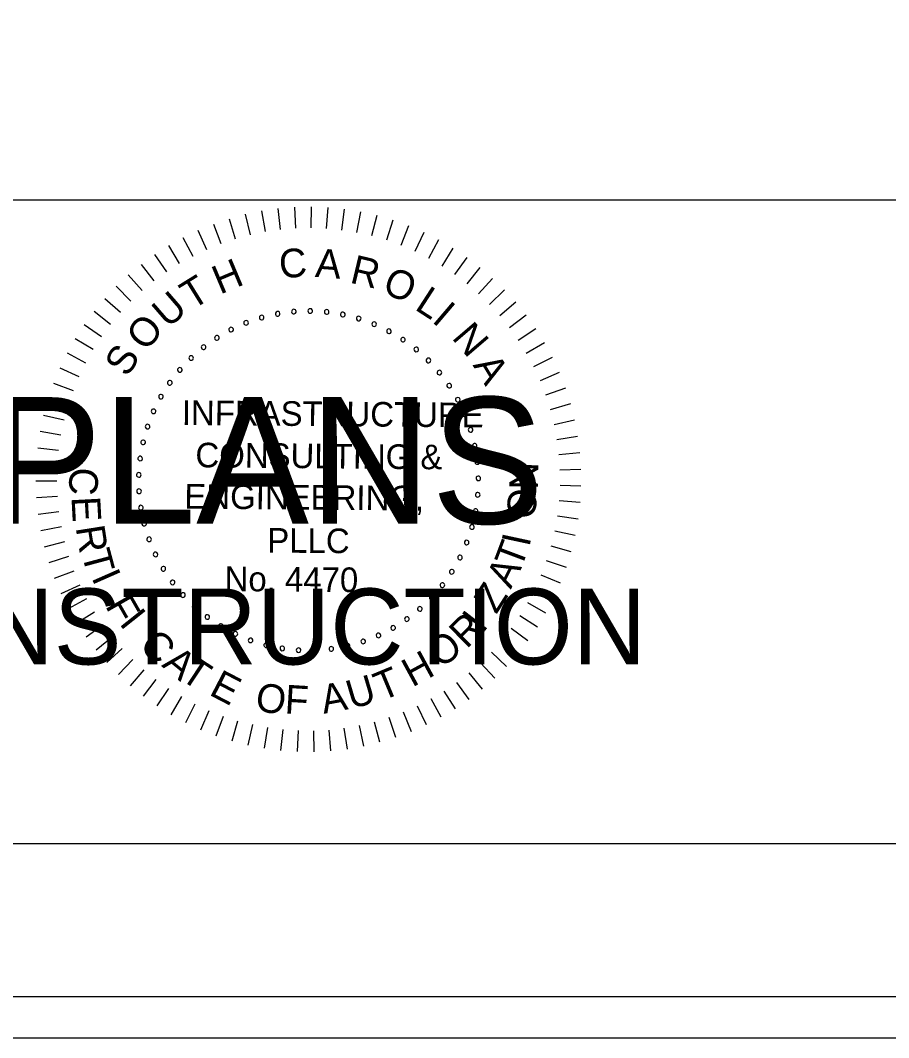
# Model space of a CAD drawing. Extents: x 967 to 1326, y 964 to 3704.
# Drawn here: x 1189.3 to 1212.88, y 2363.72 to 2391.36 of the extents above; entities that cross this region are included whole.
import ezdxf

# ---------------------------------------------------------------- set-up
doc = ezdxf.new("R2010")
doc.units = 0
for name, color, linetype in [('RD_SHT_Bndy', 7, 'Continuous'), ('RD_SHT_IplotShp', 7, 'Continuous'), ('RD_SHT_Misc1', 7, 'Continuous'), ('RD_SHT_Misc2', 7, 'Continuous'), ('RD_XS_TX_Station', 7, 'Continuous')]:
    doc.layers.add(name, color=color, linetype=linetype)

msp = doc.modelspace()

# ---------------------------------------------------------------- linework, layer by layer
at = {"layer": 'RD_SHT_Bndy'}
for p, q in [((996.114, 2386.486), (1323.886, 2386.486)), ((1323.886, 2368.983), (996.114, 2368.983))]:
    msp.add_line(p, q, dxfattribs=at)
at = {"layer": 'RD_SHT_IplotShp'}
for points in [[(967.409, 2363.72), (1326.285, 2363.72), (1326.285, 2583.72), (967.409, 2583.72)], [(988.525, 2364.84), (1326.285, 2364.84), (1326.285, 2582.6), (988.525, 2582.6)]]:
    msp.add_lwpolyline(points, close=True, dxfattribs=at)
at = {"layer": 'RD_SHT_Misc1'}
for p, q in [((1195.846, 2386.181), (1195.945, 2385.62)), ((1196.292, 2386.245), (1196.357, 2385.68)), ((1196.742, 2386.282), (1196.772, 2385.714)), ((1197.194, 2386.292), (1197.189, 2385.723)), ((1197.645, 2386.274), (1197.606, 2385.706)), ((1198.094, 2386.228), (1198.02, 2385.664)), ((1198.54, 2386.156), (1198.432, 2385.596)), ((1194.968, 2385.971), (1195.134, 2385.427)), ((1195.403, 2386.09), (1195.536, 2385.536)), ((1198.98, 2386.056), (1198.838, 2385.504)), ((1199.414, 2385.929), (1199.238, 2385.387)), ((1194.122, 2385.656), (1194.353, 2385.136)), ((1194.54, 2385.827), (1194.739, 2385.293)), ((1199.839, 2385.777), (1199.63, 2385.246)), ((1200.253, 2385.598), (1200.013, 2385.082)), ((1193.715, 2385.461), (1193.978, 2384.956)), ((1200.656, 2385.395), (1200.385, 2384.894)), ((1193.321, 2385.241), (1193.614, 2384.752)), ((1201.047, 2385.167), (1200.745, 2384.684)), ((1192.94, 2384.997), (1193.263, 2384.528)), ((1201.422, 2384.917), (1201.092, 2384.453)), ((1192.576, 2384.731), (1192.926, 2384.282)), ((1201.781, 2384.643), (1201.424, 2384.2)), ((1192.228, 2384.443), (1192.605, 2384.016)), ((1202.124, 2384.349), (1201.739, 2383.928)), ((1191.899, 2384.134), (1192.301, 2383.731)), ((1202.447, 2384.034), (1202.038, 2383.638)), ((1191.589, 2383.805), (1192.015, 2383.428)), ((1202.751, 2383.7), (1202.318, 2383.329)), ((1191.299, 2383.459), (1191.748, 2383.108)), ((1203.034, 2383.348), (1202.579, 2383.004)), ((1191.032, 2383.095), (1191.501, 2382.772)), ((1203.294, 2382.979), (1202.82, 2382.664)), ((1190.787, 2382.716), (1191.274, 2382.422)), ((1203.532, 2382.595), (1203.04, 2382.31)), ((1190.565, 2382.323), (1191.07, 2382.059)), ((1203.746, 2382.198), (1203.237, 2381.943)), ((1190.368, 2381.916), (1190.888, 2381.684)), ((1203.936, 2381.788), (1203.412, 2381.564)), ((1190.196, 2381.499), (1190.729, 2381.299)), ((1204.1, 2381.367), (1203.563, 2381.176)), ((1190.05, 2381.072), (1190.594, 2380.905)), ((1204.238, 2380.937), (1203.691, 2380.779)), ((1189.93, 2380.636), (1190.484, 2380.503)), ((1204.349, 2380.5), (1203.794, 2380.375)), ((1189.837, 2380.195), (1190.398, 2380.095)), ((1204.434, 2380.056), (1203.872, 2379.966)), ((1189.771, 2379.748), (1190.337, 2379.683)), ((1204.491, 2379.608), (1203.925, 2379.552)), ((1189.732, 2379.298), (1190.301, 2379.267)), ((1204.522, 2379.158), (1203.953, 2379.137)), ((1189.721, 2378.847), (1190.29, 2378.851)), ((1204.524, 2378.706), (1203.955, 2378.72)), ((1189.737, 2378.396), (1190.306, 2378.434)), ((1204.499, 2378.256), (1203.932, 2378.304)), ((1189.781, 2377.946), (1190.346, 2378.019)), ((1204.447, 2377.807), (1203.884, 2377.89)), ((1189.852, 2377.5), (1190.412, 2377.608)), ((1204.367, 2377.363), (1203.81, 2377.479)), ((1189.951, 2377.06), (1190.502, 2377.201)), ((1204.261, 2376.924), (1203.712, 2377.074)), ((1190.076, 2376.626), (1190.617, 2376.8)), ((1204.128, 2376.492), (1203.589, 2376.676)), ((1190.227, 2376.2), (1190.757, 2376.408)), ((1203.969, 2376.07), (1203.442, 2376.286)), ((1190.403, 2375.785), (1190.92, 2376.024)), ((1190.605, 2375.381), (1191.106, 2375.651)), ((1203.784, 2375.658), (1203.271, 2375.906)), ((1203.574, 2375.258), (1203.078, 2375.537)), ((1190.831, 2374.99), (1191.315, 2375.291)), ((1203.341, 2374.871), (1202.862, 2375.18)), ((1191.081, 2374.614), (1191.545, 2374.943)), ((1203.085, 2374.5), (1202.626, 2374.837)), ((1191.353, 2374.253), (1191.796, 2374.61)), ((1191.646, 2373.91), (1192.067, 2374.293)), ((1202.806, 2374.145), (1202.368, 2374.509)), ((1191.96, 2373.585), (1192.356, 2373.994)), ((1202.506, 2373.807), (1202.092, 2374.197)), ((1192.293, 2373.28), (1192.664, 2373.712)), ((1202.186, 2373.488), (1201.796, 2373.903)), ((1192.644, 2372.996), (1192.988, 2373.45)), ((1201.847, 2373.19), (1201.484, 2373.628)), ((1193.011, 2372.734), (1193.327, 2373.208)), ((1201.491, 2372.912), (1201.155, 2373.372)), ((1193.394, 2372.495), (1193.68, 2372.987)), ((1200.731, 2372.425), (1200.453, 2372.922)), ((1201.119, 2372.657), (1200.811, 2373.136)), ((1193.791, 2372.279), (1194.047, 2372.788)), ((1194.2, 2372.088), (1194.424, 2372.612)), ((1200.331, 2372.217), (1200.083, 2372.73)), ((1194.62, 2371.923), (1194.812, 2372.459)), ((1195.05, 2371.783), (1195.208, 2372.33)), ((1199.495, 2371.877), (1199.312, 2372.416)), ((1199.918, 2372.034), (1199.702, 2372.561)), ((1195.487, 2371.67), (1195.612, 2372.225)), ((1195.93, 2371.584), (1196.021, 2372.146)), ((1196.377, 2371.524), (1196.434, 2372.091)), ((1196.828, 2371.493), (1196.85, 2372.062)), ((1197.279, 2371.488), (1197.267, 2372.058)), ((1197.73, 2371.512), (1197.683, 2372.079)), ((1198.179, 2371.562), (1198.097, 2372.126)), ((1198.624, 2371.64), (1198.508, 2372.198)), ((1199.063, 2371.745), (1198.913, 2372.295))]:
    msp.add_line(p, q, dxfattribs=at)
for centre, start, end in [((1196.285, 2383.388), 10.6038, 190.6038), ((1196.285, 2383.388), 190.6038, 10.6038), ((1196.727, 2383.447), 5.0653, 185.0653), ((1196.727, 2383.447), 185.0653, 5.0653), ((1197.172, 2383.464), 359.5268, 179.5268), ((1197.172, 2383.464), 179.5268, 359.5268), ((1197.617, 2383.438), 173.9884, 353.9884), ((1197.617, 2383.438), 353.9884, 173.9884), ((1198.057, 2383.369), 168.4499, 348.4499), ((1198.057, 2383.369), 348.4499, 168.4499), ((1195.429, 2383.142), 21.6807, 201.6807), ((1195.429, 2383.142), 201.6807, 21.6807), ((1195.851, 2383.285), 16.1422, 196.1422), ((1195.851, 2383.285), 196.1422, 16.1422), ((1198.489, 2383.258), 162.9114, 342.9114), ((1198.489, 2383.258), 342.9114, 162.9114), ((1198.908, 2383.106), 157.373, 337.373), ((1198.908, 2383.106), 337.373, 157.373), ((1195.023, 2382.958), 27.2191, 207.2191), ((1195.023, 2382.958), 207.2191, 27.2191), ((1199.31, 2382.914), 151.8345, 331.8345), ((1199.31, 2382.914), 331.8345, 151.8345), ((1194.637, 2382.736), 32.7576, 212.7576), ((1194.637, 2382.736), 212.7576, 32.7576), ((1199.692, 2382.684), 146.2961, 326.2961), ((1199.692, 2382.684), 326.2961, 146.2961), ((1194.274, 2382.478), 38.2961, 218.2961), ((1194.274, 2382.478), 218.2961, 38.2961), ((1200.05, 2382.419), 140.7576, 320.7576), ((1200.05, 2382.419), 320.7576, 140.7576), ((1193.937, 2382.186), 43.8345, 223.8345), ((1193.937, 2382.186), 223.8345, 43.8345), ((1200.38, 2382.12), 135.2191, 315.2191), ((1200.38, 2382.12), 315.2191, 135.2191), ((1193.63, 2381.862), 49.373, 229.373), ((1193.63, 2381.862), 229.373, 49.373), ((1200.68, 2381.79), 129.6807, 309.6807), ((1200.68, 2381.79), 309.6807, 129.6807), ((1193.356, 2381.511), 54.9114, 234.9114), ((1193.356, 2381.511), 234.9114, 54.9114), ((1200.947, 2381.433), 124.1422, 304.1422), ((1200.947, 2381.433), 304.1422, 124.1422), ((1193.117, 2381.135), 60.4499, 240.4499), ((1193.117, 2381.135), 240.4499, 60.4499), ((1201.179, 2381.052), 118.6038, 298.6038), ((1201.179, 2381.052), 298.6038, 118.6038), ((1192.915, 2380.737), 65.9884, 245.9884), ((1192.915, 2380.737), 245.9884, 65.9884), ((1201.372, 2380.651), 113.0653, 293.0653), ((1201.372, 2380.651), 293.0653, 113.0653), ((1192.753, 2380.322), 71.5268, 251.5268), ((1192.753, 2380.322), 251.5268, 71.5268), ((1201.526, 2380.233), 107.5268, 287.5268), ((1201.526, 2380.233), 287.5268, 107.5268), ((1192.632, 2379.894), 77.0653, 257.0653), ((1192.632, 2379.894), 257.0653, 77.0653), ((1201.638, 2379.801), 101.9884, 281.9884), ((1201.638, 2379.801), 281.9884, 101.9884), ((1192.552, 2379.455), 82.6038, 262.6038), ((1192.552, 2379.455), 262.6038, 82.6038), ((1201.709, 2379.361), 96.4499, 276.4499), ((1201.709, 2379.361), 276.4499, 96.4499), ((1192.515, 2379.011), 88.1422, 268.1422), ((1192.515, 2379.011), 268.1422, 88.1422), ((1201.737, 2378.917), 90.9114, 270.9114), ((1201.737, 2378.917), 270.9114, 90.9114), ((1192.522, 2378.565), 93.6807, 273.6807), ((1192.522, 2378.565), 273.6807, 93.6807), ((1201.721, 2378.471), 85.373, 265.373), ((1201.721, 2378.471), 265.373, 85.373), ((1192.571, 2378.122), 99.2191, 279.2191), ((1192.571, 2378.122), 279.2191, 99.2191), ((1201.663, 2378.029), 79.8345, 259.8345), ((1201.663, 2378.029), 259.8345, 79.8345), ((1192.662, 2377.686), 104.7576, 284.7576), ((1192.662, 2377.686), 284.7576, 104.7576), ((1201.563, 2377.595), 74.2961, 254.2961), ((1201.563, 2377.595), 254.2961, 74.2961), ((1192.796, 2377.261), 110.2961, 290.2961), ((1192.796, 2377.261), 290.2961, 110.2961), ((1201.42, 2377.173), 68.7576, 248.7576), ((1201.42, 2377.173), 248.7576, 68.7576), ((1192.97, 2376.851), 115.8345, 295.8345), ((1192.97, 2376.851), 295.8345, 115.8345), ((1201.238, 2376.766), 63.2191, 243.2191), ((1201.238, 2376.766), 243.2191, 63.2191), ((1193.182, 2376.459), 121.373, 301.373), ((1193.182, 2376.459), 301.373, 121.373), ((1201.018, 2376.379), 57.6807, 237.6807), ((1201.018, 2376.379), 237.6807, 57.6807), ((1193.432, 2376.09), 126.9114, 306.9114), ((1193.432, 2376.09), 306.9114, 126.9114), ((1200.761, 2376.014), 52.1422, 232.1422), ((1200.761, 2376.014), 232.1422, 52.1422), ((1193.715, 2375.746), 132.4499, 312.4499), ((1193.715, 2375.746), 312.4499, 132.4499), ((1200.47, 2375.677), 46.6038, 226.6038), ((1200.47, 2375.677), 226.6038, 46.6038), ((1194.031, 2375.431), 137.9884, 317.9884), ((1194.031, 2375.431), 317.9884, 137.9884), ((1200.148, 2375.369), 41.0653, 221.0653), ((1200.148, 2375.369), 221.0653, 41.0653), ((1194.376, 2375.149), 143.5268, 323.5268), ((1194.376, 2375.149), 323.5268, 143.5268), ((1199.798, 2375.093), 35.5268, 215.5268), ((1199.798, 2375.093), 215.5268, 35.5268), ((1194.746, 2374.901), 149.0653, 329.0653), ((1194.746, 2374.901), 329.0653, 149.0653), ((1199.422, 2374.853), 29.9884, 209.9884), ((1199.422, 2374.853), 209.9884, 29.9884), ((1195.139, 2374.69), 154.6038, 334.6038), ((1195.139, 2374.69), 334.6038, 154.6038), ((1195.55, 2374.517), 160.1422, 340.1422), ((1195.55, 2374.517), 340.1422, 160.1422), ((1198.611, 2374.486), 18.9114, 198.9114), ((1199.026, 2374.65), 24.4499, 204.4499), ((1199.026, 2374.65), 204.4499, 24.4499), ((1195.975, 2374.386), 165.6807, 345.6807), ((1195.975, 2374.386), 345.6807, 165.6807), ((1196.412, 2374.295), 171.2191, 351.2191), ((1196.412, 2374.295), 351.2191, 171.2191), ((1196.855, 2374.248), 356.7576, 176.7576), ((1197.301, 2374.243), 2.2961, 182.2961), ((1197.745, 2374.282), 7.8345, 187.8345), ((1197.745, 2374.282), 187.8345, 7.8345), ((1198.183, 2374.363), 13.373, 193.373), ((1198.183, 2374.363), 193.373, 13.373), ((1198.611, 2374.486), 198.9114, 18.9114), ((1196.855, 2374.248), 176.7576, 356.7576), ((1197.301, 2374.243), 182.2961, 2.2961)]:
    msp.add_arc(centre, 0.0627, start, end, dxfattribs=at)
at = {"layer": 'RD_XS_TX_Station'}
msp.add_lwpolyline([(967.409, 2363.72), (1326.285, 2363.72), (1326.285, 2583.72), (967.409, 2583.72)], close=True, dxfattribs=at)

# ---------------------------------------------------------------- texts
at = {"layer": 'RD_SHT_Misc1'}
for s, height, rotation, p in [('C', 0.78, 4.7281, (1196.355, 2384.346)), ('A', 0.78, 355.6981, (1197.29, 2384.39)), ('H', 0.78, 22.7882, (1194.72, 2383.904)), ('R', 0.78, 346.6681, (1198.222, 2384.238)), ('O', 0.78, 337.638, (1199.096, 2383.972)), ('T', 0.78, 31.8182, (1193.961, 2383.478)), ('U', 0.78, 40.8482, (1193.306, 2382.976)), ('L', 0.78, 327.108, (1199.981, 2383.52)), ('I', 0.78, 319.578, (1200.451, 2383.182)), ('O', 0.78, 49.8782, (1192.707, 2382.341)), ('N', 0.78, 310.548, (1200.994, 2382.728)), ('S', 0.78, 58.9083, (1192.211, 2381.642)), ('A', 0.78, 301.5179, (1201.576, 2381.991)), ('INFRASTRUCTURE', 0.66873, 359.5268, (1193.682, 2380.367)), ('CONSULTING &', 0.66873, 359.5268, (1194.051, 2379.217)), ('N', 0.78, 89.2085, (1203.359, 2378.604)), ('C', 0.78, 267.025, (1190.646, 2379.227)), ('ENGINEERING,', 0.66873, 359.5268, (1193.751, 2378.095)), ('O', 0.78, 83.2085, (1203.26, 2377.786)), ('E', 0.78, 273.025, (1190.685, 2378.408)), ('R', 0.78, 279.025, (1190.799, 2377.583)), ('PLLC', 0.6687, 359.5268, (1196.002, 2376.9)), ('I', 0.78, 77.9093, (1203.121, 2377.032)), ('T', 0.78, 285.025, (1190.955, 2376.878)), ('T', 0.78, 69.3954, (1202.891, 2376.428)), ('No. 4470', 0.6687, 359.5268, (1194.843, 2375.855)), ('A', 0.78, 63.3954, (1202.616, 2375.888)), ('I', 0.78, 293.7713, (1191.221, 2376.225)), ('Z', 0.78, 57.3954, (1202.224, 2375.206)), ('F', 0.78, 299.7713, (1191.589, 2375.455)), ('I', 0.78, 308.5268, (1191.965, 2374.973)), ('R', 0.78, 44.5268, (1201.415, 2374.267)), ('I', 0.78, 52.3339, (1201.856, 2374.69)), ('C', 0.78, 314.5268, (1192.496, 2374.346)), ('O', 0.78, 38.5268, (1200.73, 2373.731)), ('A', 0.78, 320.5268, (1193.115, 2373.822)), ('T', 0.78, 326.5268, (1193.602, 2373.478)), ('H', 0.78, 28.5268, (1199.942, 2373.23)), ('E', 0.78, 332.5268, (1194.394, 2373.051)), ('T', 0.78, 22.5268, (1199.108, 2372.856)), ('U', 0.78, 16.5268, (1198.288, 2372.638)), ('O', 0.78, 350.5268, (1195.647, 2372.614)), ('F', 0.78, 356.5268, (1196.465, 2372.532)), ('A', 0.78, 10.5268, (1197.537, 2372.517))]:
    msp.add_text(s, height=height, rotation=rotation, dxfattribs=at).set_placement(p)
at = {"layer": 'RD_SHT_Misc2'}
for s, height, p in [('FINAL PLANS', 3.4375, (1174.145, 2377.685)), ('NOT FOR CONSTRUCTION', 2.0625, (1170.901, 2373.86))]:
    msp.add_text(s, height=height, dxfattribs=at).set_placement(p)

doc.saveas('drawing.dxf')
